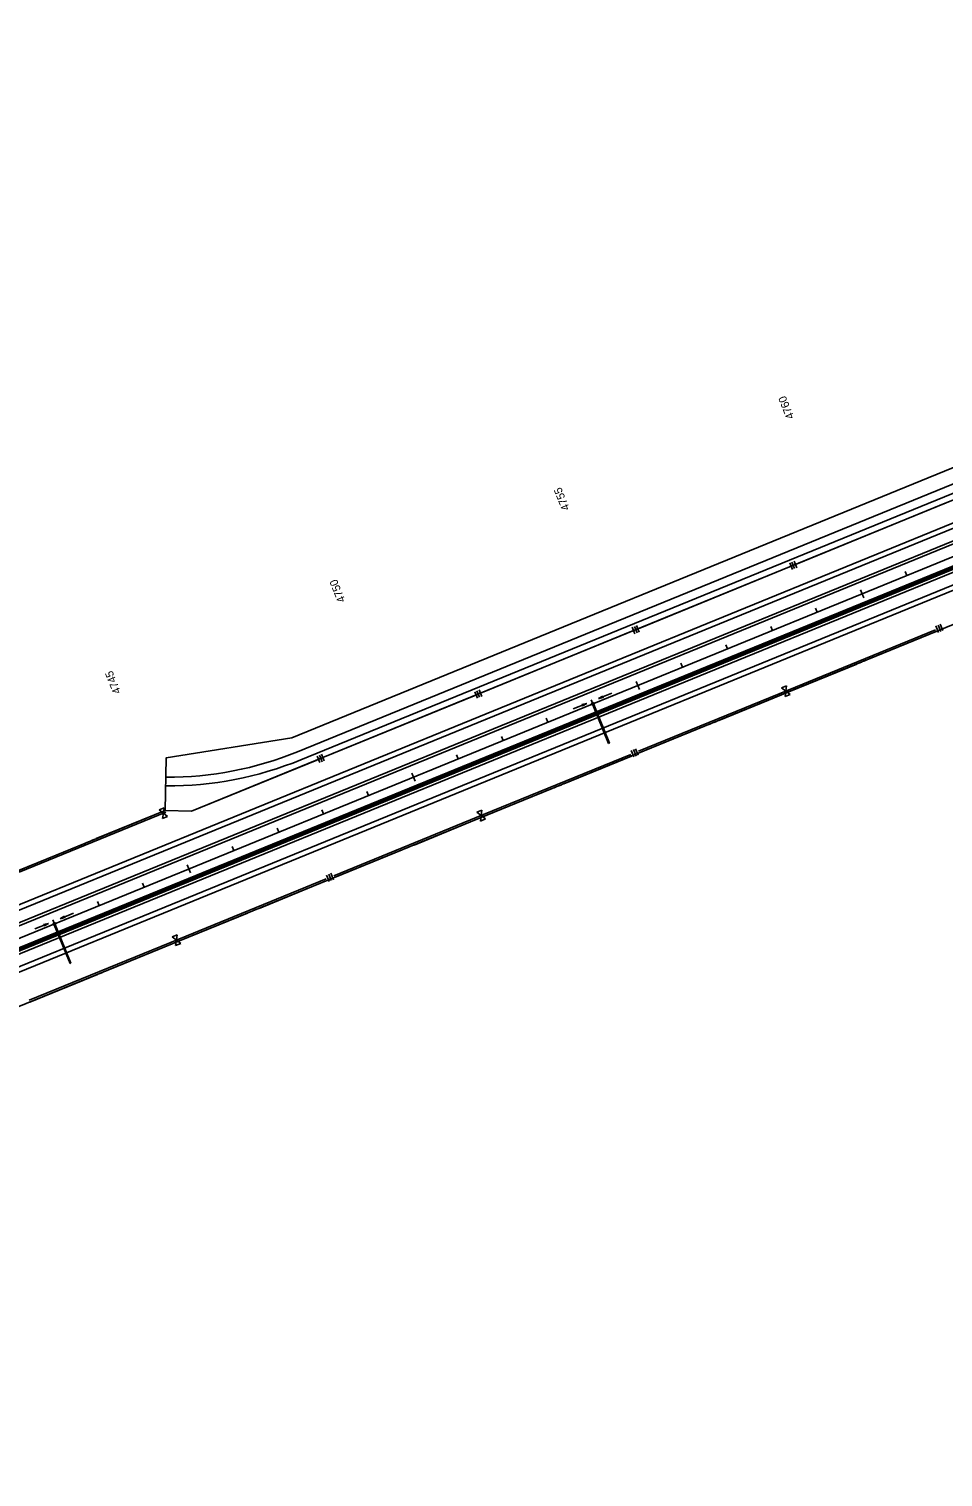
# Model space of a CAD drawing. Extents: x 192699 to 285914, y 194342 to 233219.
# Drawn here: x 221209 to 223094, y 211631 to 214616 of the extents above; entities that cross this region are included whole.
import ezdxf

# ---------------------------------------------------------------- set-up
doc = ezdxf.new("R2010")
doc.units = 0
for name, color, linetype in [('CENT LINE', 7, 'Continuous'), ('CONCRETE', 7, 'Continuous'), ('DRAINAGE', 7, 'Continuous'), ('DRAINAGE ARROWS', 7, 'Continuous'), ('R-W - CofA', 7, 'Continuous'), ('R_Water Annot', 7, 'Continuous'), ('ROAD', 7, 'Continuous'), ('SHOULDER', 7, 'Continuous'), ('STATIONING1', 7, 'Continuous'), ('WRSF', 7, 'Continuous')]:
    doc.layers.add(name, color=color, linetype=linetype)

msp = doc.modelspace()

# ---------------------------------------------------------------- linework, layer by layer
at = {"layer": 'CENT LINE'}
for p, q in [((219872.3, 212203.9), (229336.9, 216069.6)), ((221491.6, 213064.5), (221491.6, 213064.5))]:
    msp.add_line(p, q, dxfattribs=at)
at = {"layer": 'CONCRETE'}
for p, q in [((219055.3, 211850.8), (225342.4, 214418.6)), ((219056.8, 211847.1), (225343.9, 214414.9))]:
    msp.add_line(p, q, dxfattribs=at)
at = {"layer": 'DRAINAGE'}
for p, q in [((222371.7, 213222.6), (222404.2, 213143)), ((222373.6, 213223.4), (222406.1, 213143.8)), ((221260.8, 212768.9), (221293.3, 212689.3)), ((221262.7, 212769.6), (221295.2, 212690))]:
    msp.add_line(p, q, dxfattribs=at)
for points in [[(222370.8, 213222.2), (222374.5, 213223.7), (222373, 213227.4), (222369.3, 213225.9)], [(221259.9, 212768.5), (221263.6, 212770), (221262.1, 212773.7), (221258.4, 212772.2)]]:
    msp.add_lwpolyline(points, close=True, dxfattribs=at)
for points in [[(222404.2, 213143), (222406.1, 213143.8)], [(221293.3, 212689.3), (221295.2, 212690)]]:
    msp.add_lwpolyline(points, dxfattribs=at)
at = {"layer": 'DRAINAGE ARROWS'}
for p, q in [((222392.2, 213240.7), (222383.6, 213235.5)), ((222393.4, 213237.9), (222383.6, 213235.5)), ((222392.3, 213240.4), (222385.1, 213236.1)), ((222393.3, 213238.1), (222385.1, 213236.1)), ((222392.4, 213240.2), (222386.7, 213236.8)), ((222393.2, 213238.4), (222386.7, 213236.8)), ((222392.5, 213240), (222388.2, 213237.4)), ((222393.1, 213238.6), (222388.2, 213237.4)), ((222392.6, 213239.7), (222389.8, 213238.1)), ((222393, 213238.8), (222389.8, 213238.1)), ((222392.7, 213239.5), (222391.4, 213238.7)), ((222392.9, 213239.1), (222391.4, 213238.7)), ((222393.4, 213237.9), (222392.2, 213240.7)), ((222349.4, 213223.2), (222359.2, 213225.5)), ((222350.5, 213220.4), (222349.4, 213223.2)), ((222349.5, 213222.9), (222357.7, 213224.9)), ((222349.6, 213222.7), (222356.1, 213224.3)), ((222349.7, 213222.5), (222354.5, 213223.6)), ((222349.8, 213222.2), (222352.9, 213223)), ((222349.9, 213222), (222351.4, 213222.4)), ((222350, 213221.5), (222351.4, 213222.4)), ((222350.1, 213221.3), (222352.9, 213223)), ((222350.2, 213221.1), (222354.5, 213223.6)), ((222350.3, 213220.8), (222356.1, 213224.3)), ((222350.4, 213220.6), (222357.7, 213224.9)), ((222350.5, 213220.4), (222359.2, 213225.5)), ((221238.8, 212769.6), (221248.7, 212772)), ((221240, 212766.8), (221238.8, 212769.6)), ((221238.9, 212769.4), (221247.1, 212771.4)), ((221239, 212769.1), (221245.5, 212770.7)), ((221239.1, 212768.9), (221244, 212770.1)), ((221239.2, 212768.7), (221242.4, 212769.4)), ((221239.3, 212768.4), (221240.9, 212768.8)), ((221239.5, 212768), (221240.9, 212768.8)), ((221239.6, 212767.8), (221242.4, 212769.4)), ((221239.7, 212767.5), (221244, 212770.1)), ((221239.8, 212767.3), (221245.5, 212770.7)), ((221239.9, 212767.1), (221247.1, 212771.4)), ((221240, 212766.8), (221248.7, 212772)), ((221281.7, 212787.1), (221273, 212781.9)), ((221282.8, 212784.4), (221273, 212781.9)), ((221281.8, 212786.9), (221274.6, 212782.6)), ((221282.7, 212784.6), (221274.6, 212782.6)), ((221281.9, 212786.7), (221276.1, 212783.2)), ((221282.6, 212784.8), (221276.1, 212783.2)), ((221282, 212786.4), (221277.7, 212783.9)), ((221282.5, 212785.1), (221277.7, 212783.9)), ((221282.1, 212786.2), (221279.3, 212784.5)), ((221282.4, 212785.3), (221279.3, 212784.5)), ((221282.2, 212786), (221280.8, 212785.1)), ((221282.4, 212785.5), (221280.8, 212785.1)), ((221282.8, 212784.4), (221281.7, 212787.1))]:
    msp.add_line(p, q, dxfattribs=at)
at = {"layer": 'R-W - CofA'}
for p, q in [((219005, 211709.3), (225290.9, 214276.6)), ((221750.6, 213154.7), (223927.7, 214043.9)), ((222778.1, 213515.3), (222783.6, 213501.8)), ((222782.6, 213517.1), (222788.1, 213503.6)), ((222787.1, 213519), (222792.6, 213505.5)), ((222462.1, 213386.2), (222467.7, 213372.7)), ((223084.1, 213387.2), (223089.5, 213373.9)), ((223088.5, 213389), (223093.9, 213375.7)), ((222453.2, 213382.6), (222458.7, 213369.1)), ((222457.6, 213384.4), (222463.2, 213370.9)), ((223079.6, 213385.4), (223085.1, 213372.1)), ((222128.2, 213249.8), (222133.7, 213236.3)), ((222132.7, 213251.7), (222138.2, 213238.2)), ((222137.2, 213253.5), (222142.7, 213240)), ((222761, 213258), (222771.4, 213262.2)), ((222769.9, 213251.1), (222761, 213258)), ((222768.4, 213239.9), (222769.9, 213251.1)), ((222778.8, 213244.2), (222768.4, 213239.9)), ((222771.4, 213262.2), (222769.9, 213251.1)), ((222769.9, 213251.1), (222778.8, 213244.2)), ((221803.2, 213117.1), (221808.7, 213103.6)), ((221807.7, 213118.9), (221813.2, 213105.4)), ((221812.2, 213120.8), (221817.7, 213107.3)), ((222451.1, 213128.6), (222456.5, 213115.3)), ((222455.5, 213130.4), (222460.9, 213117.2)), ((222459.9, 213132.2), (222465.3, 213119)), ((218906.7, 211950), (221489.6, 213004.9)), ((221477.1, 213006.1), (221487.4, 213010.3)), ((221485.9, 212999.3), (221477.1, 213006.1)), ((221484.4, 212988.4), (221485.9, 212999.3)), ((221487.4, 213010.3), (221485.9, 212999.3)), ((221485.9, 212999.3), (221494.6, 212992.6)), ((222132.4, 213001.3), (222142.8, 213005.5)), ((222141.3, 212994.4), (222132.4, 213001.3)), ((222142.8, 213005.5), (222141.3, 212994.4)), ((221494.6, 212992.6), (221484.4, 212988.4)), ((222139.8, 212983.2), (222141.3, 212994.4)), ((222150.2, 212987.5), (222139.8, 212983.2)), ((222141.3, 212994.4), (222150.2, 212987.5)), ((221822.5, 212871.9), (221827.9, 212858.6)), ((221826.9, 212873.7), (221832.3, 212860.4)), ((221831.3, 212875.5), (221836.7, 212862.2)), ((221503.8, 212744.5), (221514.2, 212748.8)), ((221512.7, 212737.6), (221503.8, 212744.5)), ((221511.2, 212726.5), (221512.7, 212737.6)), ((221521.6, 212730.7), (221511.2, 212726.5)), ((221514.2, 212748.8), (221512.7, 212737.6)), ((221512.7, 212737.6), (221521.6, 212730.7))]:
    msp.add_line(p, q, dxfattribs=at)
for points in [[(221489.6, 213004.9), (221544.2, 213003.4), (224029.8, 214018.7), (224081.7, 214063.6)], [(222793.5, 213513.7), (223102.3, 213639.8)], [(222468.5, 213381), (222777.3, 213507.1)], [(222793.5, 213513.7), (222793.5, 213513.7)], [(222143.5, 213248.2), (222452.3, 213374.3)], [(222468.5, 213381), (222468.5, 213381)], [(222775.1, 213253.2), (223078.8, 213377.3)], [(222940.5, 213316.7), (223080.3, 213373.7)], [(222776.5, 213249.7), (222916.3, 213306.8)], [(222920.8, 213308.6), (222926.2, 213310.8)], [(222930.6, 213312.6), (222936, 213314.8)], [(221818.6, 213115.5), (222127.3, 213241.6)], [(222143.5, 213248.2), (222143.5, 213248.2)], [(222466.2, 213127), (222775.1, 213253.2)], [(222631.6, 213190.5), (222776.5, 213249.7)], [(222467.6, 213123.5), (222607.3, 213180.6)], [(222611.8, 213182.4), (222617.2, 213184.6)], [(222621.7, 213186.4), (222627.1, 213188.6)], [(221489.6, 213004.9), (221491.8, 213113.8), (221750.6, 213154.7)], [(222146.5, 212996.5), (222450.2, 213120.5)], [(221489.6, 213004.9), (221544.2, 213003.4), (221802.4, 213108.9)], [(221818.6, 213115.5), (221818.6, 213115.5)], [(222311.9, 213059.9), (222451.7, 213117)], [(222302.1, 213055.9), (222307.4, 213058.1)], [(222147.9, 212992.9), (222287.7, 213050)], [(222292.2, 213051.9), (222297.6, 213054.1)], [(221188.1, 212877.7), (221491, 213001.4)], [(221347.5, 212946.9), (221489.6, 213004.9)], [(221837.6, 212870.3), (222146.5, 212996.5)], [(222003, 212933.7), (222147.9, 212992.9)], [(221328.1, 212938.9), (221333.4, 212941.1)], [(221337.8, 212942.9), (221343.1, 212945.1)], [(221186.7, 212881.2), (221323.7, 212937.1)], [(221839, 212866.8), (221978.7, 212923.8)], [(221983.2, 212925.7), (221988.6, 212927.9)], [(221993.1, 212929.7), (221998.5, 212931.9)], [(221517.9, 212739.8), (221821.6, 212863.8)], [(221683.4, 212803.2), (221823.1, 212860.3)], [(221519.4, 212736.2), (221659.1, 212793.3)], [(221663.6, 212795.1), (221669, 212797.3)], [(221673.5, 212799.2), (221678.9, 212801.4)], [(221209, 212613.6), (221517.9, 212739.8)], [(221374.4, 212677), (221519.4, 212736.2)], [(221354.6, 212668.9), (221360, 212671.1)], [(221364.5, 212673), (221369.9, 212675.2)], [(221210.4, 212610), (221350.1, 212667.1)]]:
    msp.add_lwpolyline(points, dxfattribs=at)
at = {"layer": 'R_Water Annot'}
for p, q in [((222411.3, 213246.9), (222383.6, 213235.5)), ((222392.2, 213240.7), (222383.6, 213235.5)), ((222393.4, 213237.9), (222383.6, 213235.5)), ((222392.3, 213240.4), (222385.1, 213236.1)), ((222393.3, 213238.1), (222385.1, 213236.1)), ((222392.4, 213240.2), (222386.7, 213236.8)), ((222393.2, 213238.4), (222386.7, 213236.8)), ((222392.5, 213240), (222388.2, 213237.4)), ((222393.1, 213238.6), (222388.2, 213237.4)), ((222392.6, 213239.7), (222389.8, 213238.1)), ((222393, 213238.8), (222389.8, 213238.1)), ((222392.7, 213239.5), (222391.4, 213238.7)), ((222392.9, 213239.1), (222391.4, 213238.7)), ((222393.4, 213237.9), (222392.2, 213240.7)), ((222331.4, 213214.2), (222359.2, 213225.5)), ((222349.4, 213223.2), (222359.2, 213225.5)), ((222350.5, 213220.4), (222349.4, 213223.2)), ((222349.5, 213222.9), (222357.7, 213224.9)), ((222349.6, 213222.7), (222356.1, 213224.3)), ((222349.7, 213222.5), (222354.5, 213223.6)), ((222349.8, 213222.2), (222352.9, 213223)), ((222349.9, 213222), (222351.4, 213222.4)), ((222350, 213221.5), (222351.4, 213222.4)), ((222350.1, 213221.3), (222352.9, 213223)), ((222350.2, 213221.1), (222354.5, 213223.6)), ((222350.3, 213220.8), (222356.1, 213224.3)), ((222350.4, 213220.6), (222357.7, 213224.9)), ((222350.5, 213220.4), (222359.2, 213225.5)), ((221300.8, 212793.4), (221273, 212781.9)), ((221220.9, 212760.7), (221248.7, 212772)), ((221238.8, 212769.6), (221248.7, 212772)), ((221240, 212766.8), (221238.8, 212769.6)), ((221238.9, 212769.4), (221247.1, 212771.4)), ((221239, 212769.1), (221245.5, 212770.7)), ((221239.1, 212768.9), (221244, 212770.1)), ((221239.2, 212768.7), (221242.4, 212769.4)), ((221239.3, 212768.4), (221240.9, 212768.8)), ((221239.5, 212768), (221240.9, 212768.8)), ((221239.6, 212767.8), (221242.4, 212769.4)), ((221239.7, 212767.5), (221244, 212770.1)), ((221239.8, 212767.3), (221245.5, 212770.7)), ((221239.9, 212767.1), (221247.1, 212771.4)), ((221240, 212766.8), (221248.7, 212772)), ((221281.7, 212787.1), (221273, 212781.9)), ((221282.8, 212784.4), (221273, 212781.9)), ((221281.8, 212786.9), (221274.6, 212782.6)), ((221282.7, 212784.6), (221274.6, 212782.6)), ((221281.9, 212786.7), (221276.1, 212783.2)), ((221282.6, 212784.8), (221276.1, 212783.2)), ((221282, 212786.4), (221277.7, 212783.9)), ((221282.5, 212785.1), (221277.7, 212783.9)), ((221282.1, 212786.2), (221279.3, 212784.5)), ((221282.4, 212785.3), (221279.3, 212784.5)), ((221282.2, 212786), (221280.8, 212785.1)), ((221282.4, 212785.5), (221280.8, 212785.1)), ((221282.8, 212784.4), (221281.7, 212787.1))]:
    msp.add_line(p, q, dxfattribs=at)
at = {"layer": 'ROAD'}
for p, q in [((210661.6, 208500.3), (229316.5, 216119.6)), ((210670.7, 208478.1), (229325.6, 216097.4)), ((210702.4, 208400.3), (229357.4, 216019.6)), ((219316.1, 211944.3), (229348.3, 216041.8)), ((221762.4, 213126), (223941.4, 214016)), ((221769.2, 213109.4), (223948.2, 213999.3))]:
    msp.add_line(p, q, dxfattribs=at)
for radius in [707.2, 725.2]:
    msp.add_arc((221495, 213780.7), radius, 269.7332, 292.2167, dxfattribs=at)
at = {"layer": 'SHOULDER'}
for p, q in [((210657.8, 208509.6), (225591.1, 214608.8)), ((210691.1, 208428.1), (225763.2, 214584)), ((210672.9, 208472.5), (225606.2, 214571.8)), ((210706.2, 208391.1), (225778.4, 214547))]:
    msp.add_line(p, q, dxfattribs=at)
at = {"layer": 'STATIONING1'}
for points in [[(223016.5, 213497.9), (223019.9, 213489.5)], [(222923.9, 213460), (222930.8, 213443.4)], [(222831.4, 213422.2), (222834.8, 213413.9)], [(222738.8, 213384.4), (222742.2, 213376.1)], [(222646.2, 213346.6), (222649.6, 213338.3)], [(222553.6, 213308.8), (222557, 213300.5)], [(222461.1, 213271), (222467.9, 213254.3)], [(222368.5, 213233.2), (222371.9, 213224.8)], [(222275.9, 213195.4), (222279.3, 213187)], [(222183.3, 213157.6), (222186.7, 213149.2)], [(222090.8, 213119.7), (222094.2, 213111.4)], [(221998.2, 213081.9), (222005, 213065.3)], [(221905.6, 213044.1), (221909, 213035.8)], [(221813, 213006.3), (221816.4, 212998)], [(221720.5, 212968.5), (221723.9, 212960.2)], [(221627.9, 212930.7), (221631.3, 212922.4)], [(221535.3, 212892.9), (221542.1, 212876.2)], [(221442.7, 212855.1), (221446.1, 212846.7)], [(221350.2, 212817.3), (221353.6, 212808.9)], [(221257.6, 212779.4), (221261, 212771.1)]]:
    msp.add_lwpolyline(points, dxfattribs=at)
at = {"layer": 'WRSF'}
msp.add_line((219056, 211848.9), (225343.1, 214416.8), dxfattribs=at)

# ---------------------------------------------------------------- texts
at = {"layer": 'STATIONING1'}
for s, p in [('4760', (222787.6, 213815.7)), ('4755', (222324.5, 213627.2)), ('4750', (221861.8, 213437.6)), ('4745', (221398.7, 213249.1))]:
    msp.add_text(s, height=16.5, rotation=112.2167, dxfattribs=at).set_placement(p)

doc.saveas('drawing.dxf')
